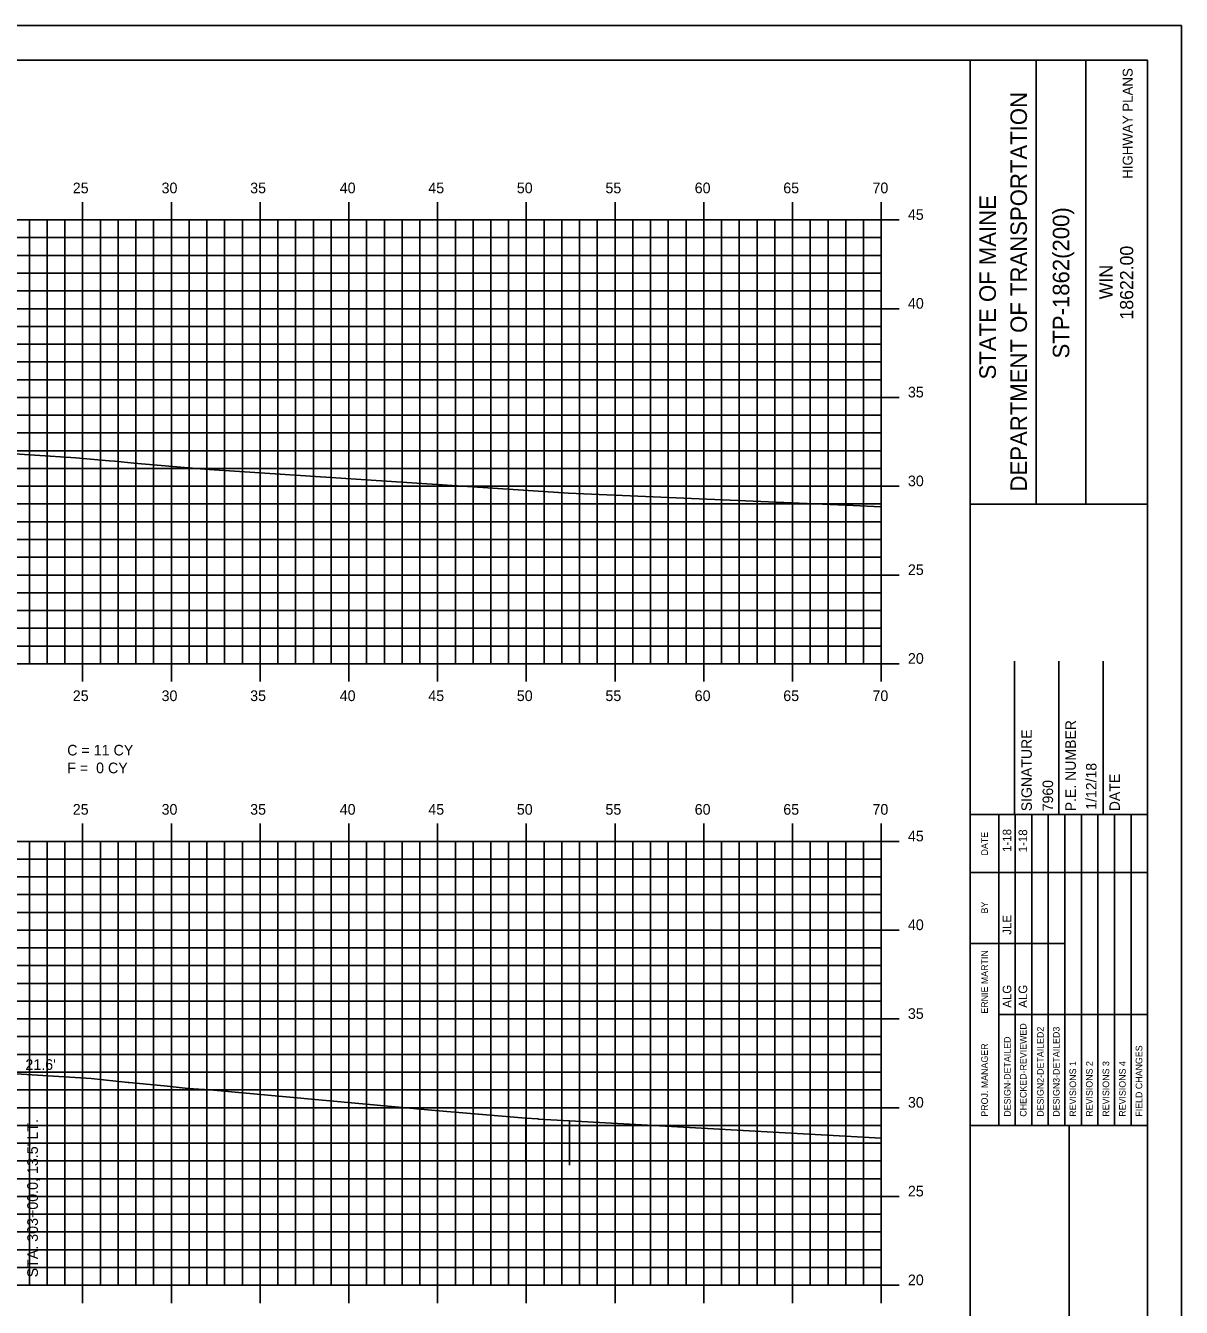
# Model space of a CAD drawing. Extents: x 1026131 to 1026301, y 394697 to 394807.
# Drawn here: x 1026236.1 to 1026301.3, y 394734.4 to 394806.5 of the extents above; entities that cross this region are included whole.
import ezdxf

# ---------------------------------------------------------------- set-up
doc = ezdxf.new("R2010")
doc.units = 0
for name, color, linetype in [('ANNOTATION', 7, 'Continuous'), ('BORDER', 7, 'Continuous'), ('D_Text_Standard', 7, 'Continuous'), ('H_V ANNOTATION', 7, 'Continuous'), ('HIGHWAY_TITLE', 7, 'Continuous'), ('MAJOR', 7, 'Continuous'), ('MINOR', 7, 'Continuous'), ('PLOT BOUNDARY', 7, 'Continuous'), ('S_Roadway_Centerline', 7, 'Continuous'), ('S_Roadway_Edge_Pavement', 7, 'Continuous')]:
    doc.layers.add(name, color=color, linetype=linetype)

msp = doc.modelspace()

# ---------------------------------------------------------------- linework, layer by layer
at = {"layer": 'BORDER'}
for p, q in [((1026299.345, 394804.607), (1026139.345, 394804.607)), ((1026289.345, 394699.607), (1026289.345, 394804.61)), ((1026293.073, 394779.604), (1026293.073, 394804.604)), ((1026295.868, 394779.604), (1026295.868, 394804.604)), ((1026299.345, 394699.607), (1026299.345, 394804.607)), ((1026289.345, 394779.601), (1026299.345, 394779.601)), ((1026291.845, 394762.11), (1026291.845, 394770.757)), ((1026294.345, 394762.11), (1026294.345, 394770.757)), ((1026296.845, 394762.11), (1026296.845, 394770.757)), ((1026289.345, 394762.11), (1026299.345, 394762.11)), ((1026289.345, 394744.61), (1026299.345, 394744.61)), ((1026294.936, 394709.61), (1026294.936, 394744.61))]:
    msp.add_line(p, q, dxfattribs=at)
for points in [[(1026290.959, 394758.86), (1026290.959, 394762.11)], [(1026291.892, 394744.613), (1026291.892, 394762.11)], [(1026292.824, 394762.11), (1026292.824, 394744.613)], [(1026293.755, 394744.613), (1026293.755, 394762.11)], [(1026294.687, 394744.613), (1026294.687, 394762.11)], [(1026295.619, 394744.613), (1026295.619, 394762.11)], [(1026296.55, 394744.613), (1026296.55, 394762.11)], [(1026297.482, 394744.613), (1026297.482, 394762.11)], [(1026298.414, 394744.613), (1026298.414, 394762.11)], [(1026290.96, 394744.613), (1026290.96, 394761.404)], [(1026289.345, 394758.86), (1026299.345, 394758.86)], [(1026289.345, 394754.86), (1026290.96, 394754.86)], [(1026290.959, 394754.86), (1026294.686, 394754.86)], [(1026290.959, 394750.86), (1026299.345, 394750.86)]]:
    msp.add_lwpolyline(points, dxfattribs=at)
at = {"layer": 'MAJOR'}
for p, q in [((1026239.344, 394796.609), (1026239.344, 394795.607)), ((1026244.344, 394796.609), (1026244.344, 394795.607)), ((1026249.344, 394796.609), (1026249.344, 394795.607)), ((1026254.344, 394796.609), (1026254.344, 394795.607)), ((1026259.344, 394796.609), (1026259.344, 394795.607)), ((1026264.344, 394796.609), (1026264.344, 394795.607)), ((1026269.344, 394796.609), (1026269.344, 394795.607)), ((1026274.344, 394796.609), (1026274.344, 394795.607)), ((1026279.344, 394796.609), (1026279.344, 394795.607)), ((1026284.344, 394796.609), (1026284.344, 394795.607)), ((1026144.344, 394795.607), (1026284.344, 394795.607)), ((1026239.344, 394770.607), (1026239.344, 394795.607)), ((1026244.344, 394770.607), (1026244.344, 394795.607)), ((1026249.344, 394770.607), (1026249.344, 394795.607)), ((1026254.344, 394770.607), (1026254.344, 394795.607)), ((1026259.344, 394770.607), (1026259.344, 394795.607)), ((1026264.344, 394770.607), (1026264.344, 394795.607)), ((1026269.344, 394770.607), (1026269.344, 394795.607)), ((1026274.344, 394770.607), (1026274.344, 394795.607)), ((1026279.344, 394770.607), (1026279.344, 394795.607)), ((1026285.346, 394795.607), (1026283.342, 394795.607)), ((1026284.344, 394770.607), (1026284.344, 394795.607)), ((1026144.344, 394790.607), (1026284.344, 394790.607)), ((1026285.346, 394790.607), (1026283.342, 394790.607)), ((1026144.344, 394785.607), (1026284.344, 394785.607)), ((1026285.346, 394785.607), (1026283.342, 394785.607)), ((1026144.344, 394780.607), (1026284.344, 394780.607)), ((1026285.346, 394780.607), (1026283.342, 394780.607)), ((1026144.344, 394775.607), (1026284.344, 394775.607)), ((1026285.346, 394775.607), (1026283.342, 394775.607)), ((1026144.344, 394770.607), (1026284.344, 394770.607)), ((1026239.344, 394769.605), (1026239.344, 394770.607)), ((1026244.344, 394769.605), (1026244.344, 394770.607)), ((1026249.344, 394769.605), (1026249.344, 394770.607)), ((1026254.344, 394769.605), (1026254.344, 394770.607)), ((1026259.344, 394769.605), (1026259.344, 394770.607)), ((1026264.344, 394769.605), (1026264.344, 394770.607)), ((1026269.344, 394769.605), (1026269.344, 394770.607)), ((1026274.344, 394769.605), (1026274.344, 394770.607)), ((1026279.344, 394769.605), (1026279.344, 394770.607)), ((1026285.346, 394770.607), (1026283.342, 394770.607)), ((1026284.344, 394769.605), (1026284.344, 394770.607)), ((1026239.344, 394761.609), (1026239.344, 394760.607)), ((1026244.344, 394761.609), (1026244.344, 394760.607)), ((1026249.344, 394761.609), (1026249.344, 394760.607)), ((1026254.344, 394761.609), (1026254.344, 394760.607)), ((1026259.344, 394761.609), (1026259.344, 394760.607)), ((1026264.344, 394761.609), (1026264.344, 394760.607)), ((1026269.344, 394761.609), (1026269.344, 394760.607)), ((1026274.344, 394761.609), (1026274.344, 394760.607)), ((1026279.344, 394761.609), (1026279.344, 394760.607)), ((1026284.344, 394761.609), (1026284.344, 394760.607)), ((1026144.344, 394760.607), (1026284.344, 394760.607)), ((1026239.344, 394735.607), (1026239.344, 394760.607)), ((1026244.344, 394735.607), (1026244.344, 394760.607)), ((1026249.344, 394735.607), (1026249.344, 394760.607)), ((1026254.344, 394735.607), (1026254.344, 394760.607)), ((1026259.344, 394735.607), (1026259.344, 394760.607)), ((1026264.344, 394735.607), (1026264.344, 394760.607)), ((1026269.344, 394735.607), (1026269.344, 394760.607)), ((1026274.344, 394735.607), (1026274.344, 394760.607)), ((1026279.344, 394735.607), (1026279.344, 394760.607)), ((1026285.346, 394760.607), (1026283.342, 394760.607)), ((1026284.344, 394735.607), (1026284.344, 394760.607)), ((1026144.344, 394755.607), (1026284.344, 394755.607)), ((1026285.346, 394755.607), (1026283.342, 394755.607)), ((1026144.344, 394750.607), (1026284.344, 394750.607)), ((1026285.346, 394750.607), (1026283.342, 394750.607)), ((1026144.344, 394745.607), (1026284.344, 394745.607)), ((1026285.346, 394745.607), (1026283.342, 394745.607)), ((1026144.344, 394740.607), (1026284.344, 394740.607)), ((1026285.346, 394740.607), (1026283.342, 394740.607)), ((1026144.344, 394735.607), (1026284.344, 394735.607)), ((1026239.344, 394734.605), (1026239.344, 394735.607)), ((1026244.344, 394734.605), (1026244.344, 394735.607)), ((1026249.344, 394734.605), (1026249.344, 394735.607)), ((1026254.344, 394734.605), (1026254.344, 394735.607)), ((1026259.344, 394734.605), (1026259.344, 394735.607)), ((1026264.344, 394734.605), (1026264.344, 394735.607)), ((1026269.344, 394734.605), (1026269.344, 394735.607)), ((1026274.344, 394734.605), (1026274.344, 394735.607)), ((1026279.344, 394734.605), (1026279.344, 394735.607)), ((1026285.346, 394735.607), (1026283.342, 394735.607)), ((1026284.344, 394734.605), (1026284.344, 394735.607))]:
    msp.add_line(p, q, dxfattribs=at)
at = {"layer": 'MINOR'}
for p, q in [((1026236.344, 394770.607), (1026236.344, 394795.607)), ((1026237.344, 394770.607), (1026237.344, 394795.607)), ((1026238.344, 394770.607), (1026238.344, 394795.607)), ((1026240.344, 394770.607), (1026240.344, 394795.607)), ((1026241.344, 394770.607), (1026241.344, 394795.607)), ((1026242.344, 394770.607), (1026242.344, 394795.607)), ((1026243.344, 394770.607), (1026243.344, 394795.607)), ((1026245.344, 394770.607), (1026245.344, 394795.607)), ((1026246.344, 394770.607), (1026246.344, 394795.607)), ((1026247.344, 394770.607), (1026247.344, 394795.607)), ((1026248.344, 394770.607), (1026248.344, 394795.607)), ((1026250.344, 394770.607), (1026250.344, 394795.607)), ((1026251.344, 394770.607), (1026251.344, 394795.607)), ((1026252.344, 394770.607), (1026252.344, 394795.607)), ((1026253.344, 394770.607), (1026253.344, 394795.607)), ((1026255.344, 394770.607), (1026255.344, 394795.607)), ((1026256.344, 394770.607), (1026256.344, 394795.607)), ((1026257.344, 394770.607), (1026257.344, 394795.607)), ((1026258.344, 394770.607), (1026258.344, 394795.607)), ((1026260.344, 394770.607), (1026260.344, 394795.607)), ((1026261.344, 394770.607), (1026261.344, 394795.607)), ((1026262.344, 394770.607), (1026262.344, 394795.607)), ((1026263.344, 394770.607), (1026263.344, 394795.607)), ((1026265.344, 394770.607), (1026265.344, 394795.607)), ((1026266.344, 394770.607), (1026266.344, 394795.607)), ((1026267.344, 394770.607), (1026267.344, 394795.607)), ((1026268.344, 394770.607), (1026268.344, 394795.607)), ((1026270.344, 394770.607), (1026270.344, 394795.607)), ((1026271.344, 394770.607), (1026271.344, 394795.607)), ((1026272.344, 394770.607), (1026272.344, 394795.607)), ((1026273.344, 394770.607), (1026273.344, 394795.607)), ((1026275.344, 394770.607), (1026275.344, 394795.607)), ((1026276.344, 394770.607), (1026276.344, 394795.607)), ((1026277.344, 394770.607), (1026277.344, 394795.607)), ((1026278.344, 394770.607), (1026278.344, 394795.607)), ((1026280.344, 394770.607), (1026280.344, 394795.607)), ((1026281.344, 394770.607), (1026281.344, 394795.607)), ((1026282.344, 394770.607), (1026282.344, 394795.607)), ((1026283.344, 394770.607), (1026283.344, 394795.607)), ((1026144.344, 394794.607), (1026284.344, 394794.607)), ((1026284.344, 394794.607), (1026283.342, 394794.607)), ((1026144.344, 394793.607), (1026284.344, 394793.607)), ((1026284.344, 394793.607), (1026283.342, 394793.607)), ((1026144.344, 394792.607), (1026284.344, 394792.607)), ((1026284.344, 394792.607), (1026283.342, 394792.607)), ((1026144.344, 394791.607), (1026284.344, 394791.607)), ((1026284.344, 394791.607), (1026283.342, 394791.607)), ((1026144.344, 394789.607), (1026284.344, 394789.607)), ((1026284.344, 394789.607), (1026283.342, 394789.607)), ((1026144.344, 394788.607), (1026284.344, 394788.607)), ((1026284.344, 394788.607), (1026283.342, 394788.607)), ((1026144.344, 394787.607), (1026284.344, 394787.607)), ((1026284.344, 394787.607), (1026283.342, 394787.607)), ((1026144.344, 394786.607), (1026284.344, 394786.607)), ((1026284.344, 394786.607), (1026283.342, 394786.607)), ((1026144.344, 394784.607), (1026284.344, 394784.607)), ((1026284.344, 394784.607), (1026283.342, 394784.607)), ((1026144.344, 394783.607), (1026284.344, 394783.607)), ((1026284.344, 394783.607), (1026283.342, 394783.607)), ((1026144.344, 394782.607), (1026284.344, 394782.607)), ((1026284.344, 394782.607), (1026283.342, 394782.607)), ((1026144.344, 394781.607), (1026284.344, 394781.607)), ((1026284.344, 394781.607), (1026283.342, 394781.607)), ((1026144.344, 394779.607), (1026284.344, 394779.607)), ((1026284.344, 394779.607), (1026283.342, 394779.607)), ((1026144.344, 394778.607), (1026284.344, 394778.607)), ((1026284.344, 394778.607), (1026283.342, 394778.607)), ((1026144.344, 394777.607), (1026284.344, 394777.607)), ((1026284.344, 394777.607), (1026283.342, 394777.607)), ((1026144.344, 394776.607), (1026284.344, 394776.607)), ((1026284.344, 394776.607), (1026283.342, 394776.607)), ((1026144.344, 394774.607), (1026284.344, 394774.607)), ((1026284.344, 394774.607), (1026283.342, 394774.607)), ((1026144.344, 394773.607), (1026284.344, 394773.607)), ((1026284.344, 394773.607), (1026283.342, 394773.607)), ((1026144.344, 394772.607), (1026284.344, 394772.607)), ((1026284.344, 394772.607), (1026283.342, 394772.607)), ((1026144.344, 394771.607), (1026284.344, 394771.607)), ((1026284.344, 394771.607), (1026283.342, 394771.607)), ((1026236.344, 394735.607), (1026236.344, 394760.607)), ((1026237.344, 394735.607), (1026237.344, 394760.607)), ((1026238.344, 394735.607), (1026238.344, 394760.607)), ((1026240.344, 394735.607), (1026240.344, 394760.607)), ((1026241.344, 394735.607), (1026241.344, 394760.607)), ((1026242.344, 394735.607), (1026242.344, 394760.607)), ((1026243.344, 394735.607), (1026243.344, 394760.607)), ((1026245.344, 394735.607), (1026245.344, 394760.607)), ((1026246.344, 394735.607), (1026246.344, 394760.607)), ((1026247.344, 394735.607), (1026247.344, 394760.607)), ((1026248.344, 394735.607), (1026248.344, 394760.607)), ((1026250.344, 394735.607), (1026250.344, 394760.607)), ((1026251.344, 394735.607), (1026251.344, 394760.607)), ((1026252.344, 394735.607), (1026252.344, 394760.607)), ((1026253.344, 394735.607), (1026253.344, 394760.607)), ((1026255.344, 394735.607), (1026255.344, 394760.607)), ((1026256.344, 394735.607), (1026256.344, 394760.607)), ((1026257.344, 394735.607), (1026257.344, 394760.607)), ((1026258.344, 394735.607), (1026258.344, 394760.607)), ((1026260.344, 394735.607), (1026260.344, 394760.607)), ((1026261.344, 394735.607), (1026261.344, 394760.607)), ((1026262.344, 394735.607), (1026262.344, 394760.607)), ((1026263.344, 394735.607), (1026263.344, 394760.607)), ((1026265.344, 394735.607), (1026265.344, 394760.607)), ((1026266.344, 394735.607), (1026266.344, 394760.607)), ((1026267.344, 394735.607), (1026267.344, 394760.607)), ((1026268.344, 394735.607), (1026268.344, 394760.607)), ((1026270.344, 394735.607), (1026270.344, 394760.607)), ((1026271.344, 394735.607), (1026271.344, 394760.607)), ((1026272.344, 394735.607), (1026272.344, 394760.607)), ((1026273.344, 394735.607), (1026273.344, 394760.607)), ((1026275.344, 394735.607), (1026275.344, 394760.607)), ((1026276.344, 394735.607), (1026276.344, 394760.607)), ((1026277.344, 394735.607), (1026277.344, 394760.607)), ((1026278.344, 394735.607), (1026278.344, 394760.607)), ((1026280.344, 394735.607), (1026280.344, 394760.607)), ((1026281.344, 394735.607), (1026281.344, 394760.607)), ((1026282.344, 394735.607), (1026282.344, 394760.607)), ((1026283.344, 394735.607), (1026283.344, 394760.607)), ((1026144.344, 394759.607), (1026284.344, 394759.607)), ((1026284.344, 394759.607), (1026283.342, 394759.607)), ((1026144.344, 394758.607), (1026284.344, 394758.607)), ((1026284.344, 394758.607), (1026283.342, 394758.607)), ((1026144.344, 394757.607), (1026284.344, 394757.607)), ((1026284.344, 394757.607), (1026283.342, 394757.607)), ((1026144.344, 394756.607), (1026284.344, 394756.607)), ((1026284.344, 394756.607), (1026283.342, 394756.607)), ((1026144.344, 394754.607), (1026284.344, 394754.607)), ((1026284.344, 394754.607), (1026283.342, 394754.607)), ((1026144.344, 394753.607), (1026284.344, 394753.607)), ((1026284.344, 394753.607), (1026283.342, 394753.607)), ((1026144.344, 394752.607), (1026284.344, 394752.607)), ((1026284.344, 394752.607), (1026283.342, 394752.607)), ((1026144.344, 394751.607), (1026284.344, 394751.607)), ((1026284.344, 394751.607), (1026283.342, 394751.607)), ((1026144.344, 394749.607), (1026284.344, 394749.607)), ((1026284.344, 394749.607), (1026283.342, 394749.607)), ((1026144.344, 394748.607), (1026284.344, 394748.607)), ((1026284.344, 394748.607), (1026283.342, 394748.607)), ((1026144.344, 394747.607), (1026284.344, 394747.607)), ((1026284.344, 394747.607), (1026283.342, 394747.607)), ((1026144.344, 394746.607), (1026284.344, 394746.607)), ((1026284.344, 394746.607), (1026283.342, 394746.607)), ((1026144.344, 394744.607), (1026284.344, 394744.607)), ((1026284.344, 394744.607), (1026283.342, 394744.607)), ((1026144.344, 394743.607), (1026284.344, 394743.607)), ((1026284.344, 394743.607), (1026283.342, 394743.607)), ((1026144.344, 394742.607), (1026284.344, 394742.607)), ((1026284.344, 394742.607), (1026283.342, 394742.607)), ((1026144.344, 394741.607), (1026284.344, 394741.607)), ((1026284.344, 394741.607), (1026283.342, 394741.607)), ((1026144.344, 394739.607), (1026284.344, 394739.607)), ((1026284.344, 394739.607), (1026283.342, 394739.607)), ((1026144.344, 394738.607), (1026284.344, 394738.607)), ((1026284.344, 394738.607), (1026283.342, 394738.607)), ((1026144.344, 394737.607), (1026284.344, 394737.607)), ((1026284.344, 394737.607), (1026283.342, 394737.607)), ((1026144.344, 394736.607), (1026284.344, 394736.607)), ((1026284.344, 394736.607), (1026283.342, 394736.607))]:
    msp.add_line(p, q, dxfattribs=at)
at = {"layer": 'PLOT BOUNDARY'}
msp.add_lwpolyline([(1026131.251, 394696.548), (1026301.251, 394696.548), (1026301.251, 394806.548), (1026131.251, 394806.548)], close=True, dxfattribs=at)
at = {"layer": 'S_Roadway_Centerline'}
for points in [[(1026227.396, 394782.948), (1026238.957, 394782.214), (1026239.999, 394782.108), (1026240.84, 394782.036), (1026241.158, 394782.016), (1026242.229, 394781.909), (1026245.96, 394781.592), (1026246.467, 394781.541), (1026262.453, 394780.498), (1026266.721, 394780.222), (1026282.758, 394779.524), (1026284.344, 394779.453)], [(1026233.45, 394747.649), (1026239.83, 394747.244), (1026241.906, 394747.031), (1026241.956, 394747.027), (1026241.974, 394747.026), (1026244.123, 394746.811), (1026244.283, 394746.797), (1026245.288, 394746.696), (1026246.521, 394746.616), (1026259.212, 394745.441), (1026264.308, 394745.024), (1026264.967, 394744.971), (1026265.027, 394744.978), (1026265.027, 394744.968), (1026266.767, 394744.87), (1026284.344, 394743.891)]]:
    msp.add_lwpolyline(points, dxfattribs=at)
at = {"layer": 'S_Roadway_Edge_Pavement'}
for p, q in [((1026264.308, 394745.024), (1026264.308, 394742.524)), ((1026266.767, 394744.87), (1026266.767, 394742.37))]:
    msp.add_line(p, q, dxfattribs=at)

# ---------------------------------------------------------------- texts
at = {"layer": 'ANNOTATION'}
for s, p in [('C = 11 CY', (1026238.476, 394765.442)), ('F =  0 CY', (1026238.476, 394764.442))]:
    msp.add_text(s, height=0.6, dxfattribs=at).set_placement(p)
msp.add_text("STA. 303+00.0, 13.5' LT.", height=0.6, rotation=90, dxfattribs=at).set_placement((1026236.824, 394736.048))
at = {"layer": 'BORDER'}
for s, height, p in [('DEPARTMENT OF TRANSPORTATION', 0.93176, (1026292.551, 394780.313)), ('STATE OF MAINE', 0.93176, (1026290.8, 394786.619)), ('STP-1862(200)', 0.93176, (1026294.936, 394787.801)), ('18622.00', 0.7453, (1026298.54, 394789.993)), ('WIN', 0.7453, (1026297.381, 394791.137)), ('SIGNATURE', 0.5906, (1026292.825, 394762.302)), ('P.E. NUMBER', 0.59055, (1026295.305, 394762.302)), ('1/12/18', 0.5906, (1026296.468, 394762.389)), ('7960', 0.5906, (1026294.022, 394762.302)), ('DATE', 0.5906, (1026297.786, 394762.302)), ('DATE', 0.3714, (1026290.349, 394759.815)), ('1-18', 0.4845, (1026291.667, 394760.007)), ('1-18', 0.4845, (1026292.562, 394759.985)), ('BY', 0.3714, (1026290.349, 394756.545)), ('JLE', 0.4845, (1026291.667, 394755.345)), ('ERNIE MARTIN', 0.37275, (1026290.349, 394750.901)), ('ALG', 0.4845, (1026291.667, 394751.233)), ('ALG', 0.4845, (1026292.562, 394751.233)), ('CHECKED-REVIEWED', 0.37275, (1026292.526, 394745.098)), ('DESIGN-DETAILED', 0.37275, (1026291.631, 394745.098)), ('DESIGN2-DETAILED2', 0.37275, (1026293.494, 394745.098)), ('DESIGN3-DETAILED3', 0.37275, (1026294.389, 394745.098)), ('PROJ. MANAGER', 0.37275, (1026290.349, 394745.098)), ('FIELD CHANGES', 0.37275, (1026299.047, 394745.098)), ('REVISIONS 1', 0.37275, (1026295.321, 394745.098)), ('REVISIONS 2', 0.37275, (1026296.252, 394745.098)), ('REVISIONS 3', 0.37275, (1026297.184, 394745.098)), ('REVISIONS 4', 0.37275, (1026298.116, 394745.098))]:
    msp.add_text(s, height=height, rotation=90, dxfattribs=at).set_placement(p)
at = {"layer": 'D_Text_Standard'}
msp.add_text("21.6'", height=0.6, dxfattribs=at).set_placement((1026236.121, 394747.735))
at = {"layer": 'H_V ANNOTATION'}
for s, p in [('25', (1026238.79, 394797.107)), ('30', (1026243.793, 394797.107)), ('35', (1026248.785, 394797.107)), ('40', (1026253.83, 394797.107)), ('45', (1026258.822, 394797.107)), ('50', (1026263.809, 394797.107)), ('55', (1026268.801, 394797.107)), ('60', (1026273.83, 394797.107)), ('65', (1026278.822, 394797.107)), ('70', (1026283.846, 394797.107)), ('45', (1026285.844, 394795.607)), ('40', (1026285.844, 394790.607)), ('35', (1026285.844, 394785.607)), ('30', (1026285.844, 394780.607)), ('25', (1026285.844, 394775.607)), ('20', (1026285.844, 394770.607)), ('25', (1026238.79, 394768.507)), ('30', (1026243.793, 394768.507)), ('35', (1026248.785, 394768.507)), ('40', (1026253.83, 394768.507)), ('45', (1026258.822, 394768.507)), ('50', (1026263.809, 394768.507)), ('55', (1026268.801, 394768.507)), ('60', (1026273.83, 394768.507)), ('65', (1026278.822, 394768.507)), ('70', (1026283.846, 394768.507)), ('25', (1026238.79, 394762.107)), ('30', (1026243.793, 394762.107)), ('35', (1026248.785, 394762.107)), ('40', (1026253.83, 394762.107)), ('45', (1026258.822, 394762.107)), ('50', (1026263.809, 394762.107)), ('55', (1026268.801, 394762.107)), ('60', (1026273.83, 394762.107)), ('65', (1026278.822, 394762.107)), ('70', (1026283.846, 394762.107)), ('45', (1026285.844, 394760.607)), ('40', (1026285.844, 394755.607)), ('35', (1026285.844, 394750.607)), ('30', (1026285.844, 394745.607)), ('25', (1026285.844, 394740.607)), ('20', (1026285.844, 394735.607))]:
    msp.add_text(s, height=0.6, dxfattribs=at).set_placement(p)
at = {"layer": 'HIGHWAY_TITLE'}
msp.add_text('HIGHWAY PLANS', height=0.55901, rotation=90, dxfattribs=at).set_placement((1026298.503, 394797.922))

doc.saveas('drawing.dxf')
